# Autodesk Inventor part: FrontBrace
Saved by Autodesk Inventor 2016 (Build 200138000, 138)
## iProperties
Created: 2016-01
Part Number: FrontBrace
Material: Generic
Document SubType Name: Modeling
Designer: John
Density: 1 g/cm^3
Appearance: Default
Author: John
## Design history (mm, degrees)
feature "Base1"
body "Solid1"
